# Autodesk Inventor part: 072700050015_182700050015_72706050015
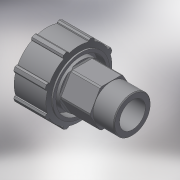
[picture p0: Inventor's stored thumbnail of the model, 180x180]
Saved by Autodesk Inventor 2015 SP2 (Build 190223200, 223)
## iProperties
Created: 2017-04
Part Number: 072700050015_182700050015_72706050015
Material: Generic
Description: PLASSON BRASS THREADED ADAPTOR 50-1.1/2"
Document SubType Name: Modeling
Designer: KIM
Density: 1 g/cm^3
Appearance: Default
Author: KIM
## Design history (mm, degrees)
derived "07270.ipt"
feature "Solid1::07270.ipt"
tag "TaggingFeature1"
body "Solid1"
other parameters: "d1" = 47.803, "d2" = 97, "d3" = 21, "d7" = 96, "d8" = 76.8, "d12" = 33.4621, "d13" = 38.2424, "d15" = 72, "d17" = 38.8, "d18" = 21, "d19" = 25.2, "d40" = 52, "d41" = 59.8, "d42" = 135 deg, "d43" = 100 deg, "d44" = 35.696, "d45" = 68.4, "d46" = 89.28, "d47" = 35 deg, "d48" = 17.5 deg, "d50" = 0, "d52" = 360 deg, "d54" = 1.92, "d57" = 1.92, "d61" = 0, "d62" = 0.95606, "d65" = 1.43409, "R_" = 47.803, "E_" = 96, "H_" = 97, "l_2" = 21, "Wrench" = 52
